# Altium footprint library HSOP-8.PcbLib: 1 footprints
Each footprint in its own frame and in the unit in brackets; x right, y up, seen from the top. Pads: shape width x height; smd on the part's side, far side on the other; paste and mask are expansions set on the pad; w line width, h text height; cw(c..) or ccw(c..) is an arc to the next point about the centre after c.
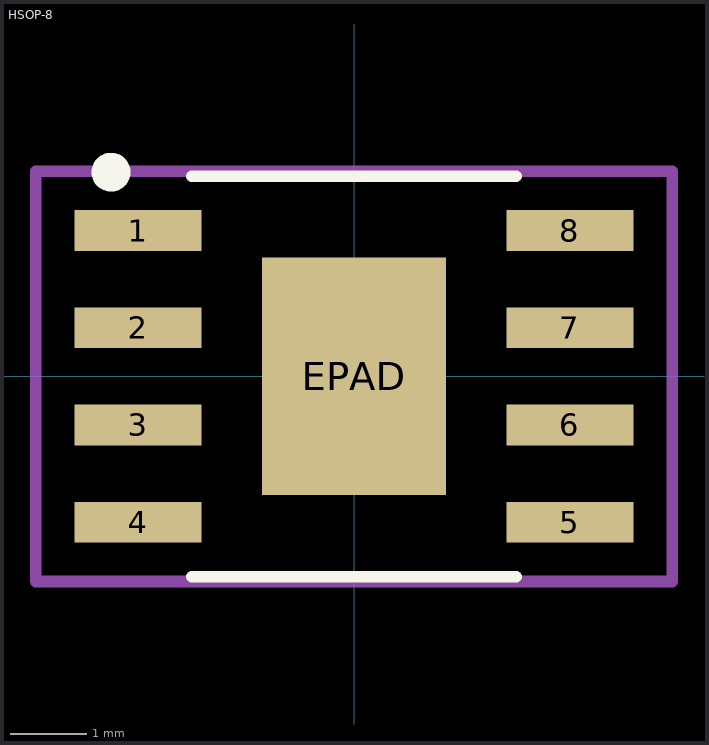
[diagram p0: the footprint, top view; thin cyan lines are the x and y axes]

## HSOP-8 [mm]
pads (9):
  rect 1.655x0.533 smd: 1(-2.821,1.905) 2(-2.821,0.635) 3(-2.821,-0.635) 4(-2.821,-1.905) 5(2.821,-1.905) 6(2.821,-0.635) 7(2.821,0.635) 8(2.821,1.905)
  rect 2.4x3.1 smd: EPAD(0,0)
Top Overlay:
  circle w0.254: c-3.175,2.667 r0.127
  lines w0.152: -2.121,-2.616 2.121,-2.616 ; -2.121,2.616 2.121,2.616
Top Paste:
  region: 1.1,1.45 -1.1,1.45 -1.1,0.1 1.1,0.1
  region: 1.1,-0.1 -1.1,-0.1 -1.1,-1.45 1.1,-1.45
Mechanical 15:
  lines w0.152: -4.157,-2.679 -4.157,2.679 -2.502,2.679 2.502,2.679 4.157,2.679 4.157,-2.679 2.502,-2.679 -2.502,-2.679 -4.157,-2.679
3D body "DDA8_3P1X2P4_TEX.step": height 1.68, standoff -0.05, extent -3.099,-2.489 3.099,2.489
